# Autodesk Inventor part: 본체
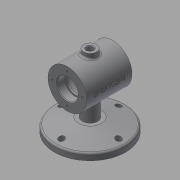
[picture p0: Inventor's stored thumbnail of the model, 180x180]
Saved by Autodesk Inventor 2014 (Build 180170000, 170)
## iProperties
Created: 2018-12
Part Number: 본체
Material: Generic
Document SubType Name: Modeling
Designer: kh
Density: 1 g/cm^3
Appearance: Default
Author: kh
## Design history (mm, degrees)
sketch "Sketch1"
  geometry: C1 r 55 at (0, 0); 1 further point
  constraints: 1 centre point, 1 coincident
  dimensions: "d0" = 110 diameter of C1
extrude "Extrusion1" new body sketch "Sketch1" distance "d1" = 10; taper "d2" = 0 deg
sketch "Sketch2"
  geometry: C1 r 55 at (0, 0); 1 further point
  constraints: 1 centre point, 1 coincident
  dimensions: "d3" = 110 diameter of C1
extrude "Extrusion2" join sketch "Sketch2" distance "d4" = 10; taper "d5" = -75 deg
sketch "Sketch4"
  geometry: L1 (0, 0)-(0, 75); C1 r 30 at (0, 75)
  constraints: 2 end point, 1 centre point, 1 coincident, 1 vertical
  dimensions: "d9" = 75 distance of L1.start L1.end; "d10" = 60 diameter of C1
extrude "Extrusion3" join sketch "Sketch4" stored distance "d11" = 70; taper "d12" = 0 deg
sketch "Sketch5"
  geometry: L1 (-35, 105)-(-35, 45) reference; L2 (-35, 75)-(35.231, 75); L3 (-35, 75)-(-35, 91); L4 (-35, 91)-(-23, 91); L5 (-23, 91)-(-23, 89); L6 (-23, 89)-(-20, 89); L7 (-20, 89)-(-20, 100); L8 (-20, 100)-(20, 100); L9 (20, 100)-(20, 89); L10 (20, 89)-(23, 89); L11 (23, 89)-(23, 91); L12 (35, 45)-(35, 105) reference; L13 (23, 91)-(35, 91); L14 (35, 75)-(35, 91); L15 (-35, 75)-(35, 75); 1 further point
  constraints: 26 end point, 6 parallel, 4 perpendicular, 2 midpoint, 2 point on line, 1 collinear
  dimensions: "d13" = 75 distance from line of L2 point (0, 0); "d14" = 12 distance between parallel lines of L5 L3; "d15" = 12 distance of L11.end L13.end; "d16" = 3 distance of L5.end L6.end; "d17" = 40 distance of L7.end L8.end; "d18" = 32 diameter of L4 L2; "d19" = 28 diameter of L6 L2; "d20" = 50 diameter of L8 L2; "d21" = 28 diameter of L10 L2; "d22" = 32 diameter of L13 L2
revolve "Revolution1" sketch "Sketch5" stored, may be unused: angle "d23" = 90 deg
sketch "Sketch6"
  geometry: C1 r 12 at (0, 0); 1 further point
  constraints: 1 centre point, 1 coincident
  dimensions: "d24" = 24 diameter of C1
extrude "Extrusion4" join sketch "Sketch6" stored distance "d25" = 10; taper "d26" = 0 deg
chamfer "Chamfer1" distance "d27" = 1; stored, may be unused: second distance "d28" = 2, angle "d29" = 45 deg
fillet "Fillet1" dims "d30" = 0.3, "d31" = 3
sketch "Sketch7" dims "d32" = 46
  geometry: L1 (0, 0)-(0, 23); C1 r 17 at (0, 0) reference; 8 further points
  constraints: 5 coincident, 2 end point, 1 vertical, 1 vertical alignment, 11 other
  dimensions: "d35" = 360 deg dimension on C1.centre L1.end (derived)
hole "Hole1" sketch "Sketch7" at (0, 23), (-23, 0), (0, -23), (23, 0) diameter "d37" = 3.242; stored, may be unused: countersink angle "d41" = 90 deg, drill point angle "d43" = 118 deg; dims "d38" = 8, "d39" = 4, "d40" = 2, "d42" = 10
mirror "Mirror1"
fillet "Fillet2" dims "d49" = 3
workplane "Work Plane2"
sketch "Sketch9"
  geometry: C1 r 10 at (0, 0); C2 r 5 at (0, 0); 1 further point
  constraints: 2 centre point, 2 coincident
  dimensions: "d51" = 20 diameter of C1; "d54" = 10 diameter of C2
extrude "Extrusion5" join sketch "Sketch9" stored distance "d52" = 10; taper "d53" = 0 deg
extrude "Extrusion6" cut sketch "Sketch9" distance "d55" = 30; taper "d56" = 0 deg
chamfer "Chamfer2" distance "d57" = 1; stored, may be unused: second distance "d58" = 2, angle "d59" = 45 deg
fillet "Fillet3" dims "d60" = 3
workplane "Work Plane3"
sketch "Sketch10"
  geometry: L1 (-35, 105)-(-35, 45) reference; L2 (-35, 75)-(25.972, 75); L3 (-35, 105)-(35, 105) reference; L4 (10, 112)-(-10, 112) reference; L5 (0, 112)-(0, 75); L6 (-24.763, 79.724)-(25.011, 79.724); L7 (25.011, 79.724)-(25.011, 72.519); L8 (25.011, 72.519)-(-24.763, 72.519); L9 (-24.763, 72.519)-(-24.763, 79.724); 1 further point
  constraints: 4 end point, 2 midpoint, 2 perpendicular, 1 point on line, 2 other
emboss "Emboss1" sketch "Sketch10" dims "d1" = 10, "d2" = 0, "d13" = 75, "d14" = 12, "d15" = 12, "d16" = 3, "d17" = 40, "d18" = 32, "d19" = 28, "d20" = 50, "d21" = 28, "d22" = 32, "d62" = 0.5, "d63" = 0
sketch "Sketch11" dims "d64" = 88
  geometry: C1 r 55 at (0, 0) reference; 6 further points
  constraints: 1 coincident, 1 vertical alignment, 7 other
  dimensions: "d67" = 360 deg dimension on point (0, 0) point (0, 44) (derived)
hole "Hole2" sketch "Sketch11" at (0, 44), (-44, 0), (0, -44), (44, 0) diameter "d69" = 9; stored, may be unused: countersink angle "d73" = 90 deg, drill point angle "d75" = 118 deg; dims "d70" = 10, "d71" = 14, "d72" = 2, "d74" = 10
workplane "Work Plane4"
sketch "Sketch12" dims "d77" = 88
  geometry: L1 (0, 0)-(0, 44); C1 r 55 at (0, 0) reference; 5 further points
  constraints: 2 coincident, 2 end point, 1 vertical, 1 vertical alignment, 7 other
  dimensions: "d80" = 360 deg dimension on point (0, 0) point (0, 44) (derived)
body "Solid1"
other parameters: "d50" = -112, "d61" = 94.5
